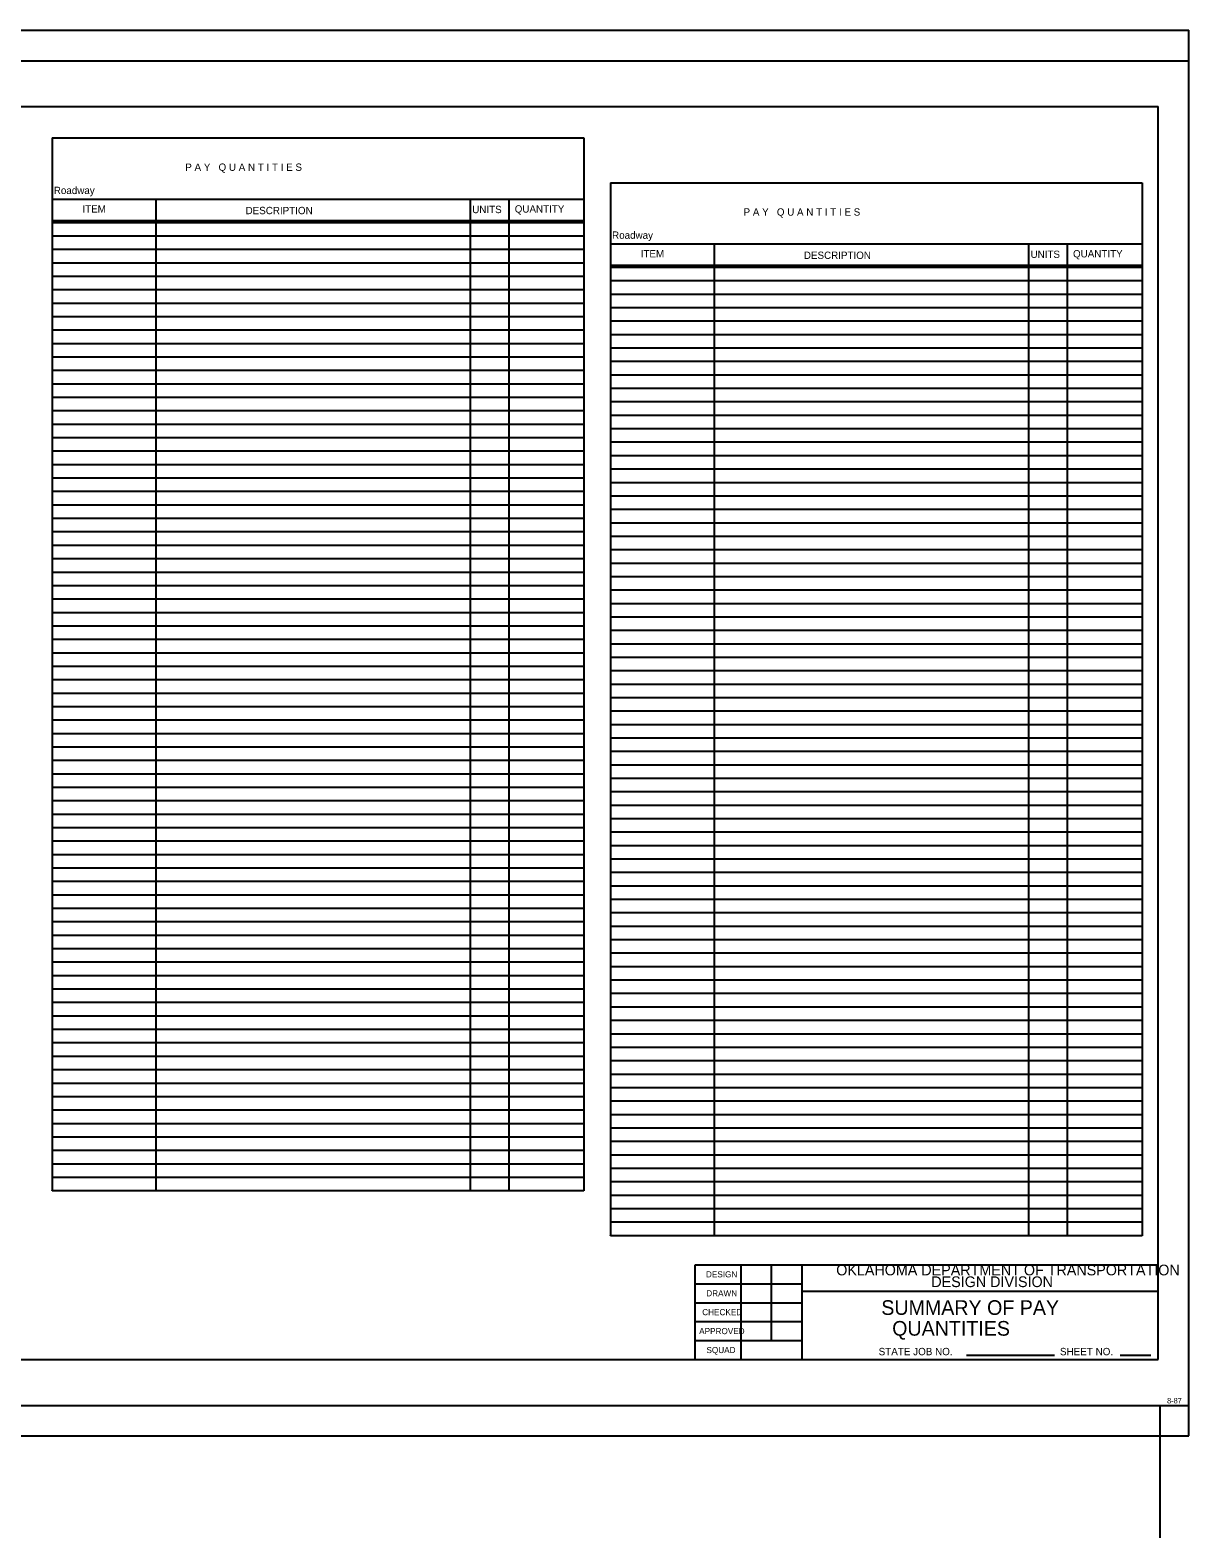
# Model space of a CAD drawing. Extents: x 1789800 to 1793399, y 1789140 to 1791776.
# Drawn here: x 1791505 to 1793399, y 1789140 to 1791606 of the extents above; entities that cross this region are included whole.
import ezdxf

# ---------------------------------------------------------------- set-up
doc = ezdxf.new("R2010")
doc.units = 0
for name, color, linetype in [('Level 1', 7, 'Continuous'), ('Level 2', 7, 'Continuous'), ('Level 20', 7, 'Continuous'), ('Level 21', 7, 'Continuous')]:
    doc.layers.add(name, color=color, linetype=linetype)

msp = doc.modelspace()

# ---------------------------------------------------------------- linework, layer by layer
at = {"layer": 'Level 2'}
for p, q in [((1791540.9, 1791430.2), (1792410.2, 1791430.2)), ((1791540.9, 1791430.2), (1791540.9, 1789707.4)), ((1792410.2, 1791430.2), (1792410.2, 1789707.4)), ((1792453.7, 1791356.9), (1793323.1, 1791356.9)), ((1792453.7, 1791356.9), (1792453.7, 1789634.2)), ((1793323.1, 1791356.9), (1793323.1, 1789634.2)), ((1791540.9, 1791330.2), (1792410.2, 1791330.2)), ((1791710.2, 1791330.2), (1791710.2, 1789708)), ((1792224.2, 1791330.2), (1792224.2, 1789708)), ((1792287.7, 1791329.9), (1792287.7, 1789707.6)), ((1791540.9, 1791295.2), (1792410.2, 1791295.2)), ((1791540.9, 1791292), (1792410.2, 1791292)), ((1791540.9, 1791270), (1792410.2, 1791270)), ((1792453.7, 1791256.9), (1793323.1, 1791256.9)), ((1792623.1, 1791256.9), (1792623.1, 1789634.7)), ((1793137.1, 1791256.9), (1793137.1, 1789634.7)), ((1793200.6, 1791256.6), (1793200.6, 1789634.4)), ((1791540.9, 1791248), (1792410.2, 1791248)), ((1791540.9, 1791226), (1792410.2, 1791226)), ((1792453.7, 1791221.9), (1793323.1, 1791221.9)), ((1792453.7, 1791218.7), (1793323.1, 1791218.7)), ((1791540.9, 1791204), (1792410.2, 1791204)), ((1791540.9, 1791182), (1792410.2, 1791182)), ((1792453.7, 1791196.7), (1793323.1, 1791196.7)), ((1791540.9, 1791160), (1792410.2, 1791160)), ((1792453.7, 1791174.7), (1793323.1, 1791174.7)), ((1791540.9, 1791138), (1792410.2, 1791138)), ((1792453.7, 1791152.7), (1793323.1, 1791152.7)), ((1791540.9, 1791116), (1792410.2, 1791116)), ((1792453.7, 1791130.7), (1793323.1, 1791130.7)), ((1792453.7, 1791108.7), (1793323.1, 1791108.7)), ((1791540.9, 1791094), (1792410.2, 1791094)), ((1792453.7, 1791086.7), (1793323.1, 1791086.7)), ((1791540.9, 1791072), (1792410.2, 1791072)), ((1792453.7, 1791064.7), (1793323.1, 1791064.7)), ((1791540.9, 1791050), (1792410.2, 1791050)), ((1792453.7, 1791042.7), (1793323.1, 1791042.7)), ((1791540.9, 1791028), (1792410.2, 1791028)), ((1792453.7, 1791020.7), (1793323.1, 1791020.7)), ((1791540.9, 1791006), (1792410.2, 1791006)), ((1791540.9, 1790984), (1792410.2, 1790984)), ((1792453.7, 1790998.7), (1793323.1, 1790998.7)), ((1791540.9, 1790962), (1792410.2, 1790962)), ((1792453.7, 1790976.7), (1793323.1, 1790976.7)), ((1791540.9, 1790940), (1792410.2, 1790940)), ((1792453.7, 1790954.7), (1793323.1, 1790954.7)), ((1791540.9, 1790918), (1792410.2, 1790918)), ((1792453.7, 1790932.7), (1793323.1, 1790932.7)), ((1792453.7, 1790910.7), (1793323.1, 1790910.7)), ((1791540.9, 1790896), (1792410.2, 1790896)), ((1792453.7, 1790888.7), (1793323.1, 1790888.7)), ((1791540.9, 1790874), (1792410.2, 1790874)), ((1792453.7, 1790866.7), (1793323.1, 1790866.7)), ((1791540.9, 1790852), (1792410.2, 1790852)), ((1792453.7, 1790844.7), (1793323.1, 1790844.7)), ((1791540.9, 1790830), (1792410.2, 1790830)), ((1792453.7, 1790822.7), (1793323.1, 1790822.7)), ((1791540.9, 1790808), (1792410.2, 1790808)), ((1792453.7, 1790800.7), (1793323.1, 1790800.7)), ((1791540.9, 1790786), (1792410.2, 1790786)), ((1791540.9, 1790764), (1792410.2, 1790764)), ((1792453.7, 1790778.7), (1793323.1, 1790778.7)), ((1791540.9, 1790742), (1792410.2, 1790742)), ((1792453.7, 1790756.7), (1793323.1, 1790756.7)), ((1791540.9, 1790720), (1792410.2, 1790720)), ((1792453.7, 1790734.7), (1793323.1, 1790734.7)), ((1792453.7, 1790712.7), (1793323.1, 1790712.7)), ((1791540.9, 1790698), (1792410.2, 1790698)), ((1792453.7, 1790690.7), (1793323.1, 1790690.7)), ((1791540.9, 1790676), (1792410.2, 1790676)), ((1792453.7, 1790668.7), (1793323.1, 1790668.7)), ((1791540.9, 1790654), (1792410.2, 1790654)), ((1792453.7, 1790646.7), (1793323.1, 1790646.7)), ((1791540.9, 1790632), (1792410.2, 1790632)), ((1792453.7, 1790624.7), (1793323.1, 1790624.7)), ((1791540.9, 1790610), (1792410.2, 1790610)), ((1792453.7, 1790602.7), (1793323.1, 1790602.7)), ((1791540.9, 1790588), (1792410.2, 1790588)), ((1791540.9, 1790566), (1792410.2, 1790566)), ((1792453.7, 1790580.7), (1793323.1, 1790580.7)), ((1791540.9, 1790544), (1792410.2, 1790544)), ((1792453.7, 1790558.7), (1793323.1, 1790558.7)), ((1791540.9, 1790522), (1792410.2, 1790522)), ((1792453.7, 1790536.7), (1793323.1, 1790536.7)), ((1791540.9, 1790500), (1792410.2, 1790500)), ((1792453.7, 1790514.7), (1793323.1, 1790514.7)), ((1792453.7, 1790492.7), (1793323.1, 1790492.7)), ((1791540.9, 1790478), (1792410.2, 1790478)), ((1792453.7, 1790470.7), (1793323.1, 1790470.7)), ((1791540.9, 1790456), (1792410.2, 1790456)), ((1792453.7, 1790448.7), (1793323.1, 1790448.7)), ((1791540.9, 1790434), (1792410.2, 1790434)), ((1792453.7, 1790426.7), (1793323.1, 1790426.7)), ((1791540.9, 1790412), (1792410.2, 1790412)), ((1792453.7, 1790404.7), (1793323.1, 1790404.7)), ((1791540.9, 1790390), (1792410.2, 1790390)), ((1791540.9, 1790368), (1792410.2, 1790368)), ((1792453.7, 1790382.7), (1793323.1, 1790382.7)), ((1791540.9, 1790346), (1792410.2, 1790346)), ((1792453.7, 1790360.7), (1793323.1, 1790360.7)), ((1791540.9, 1790324), (1792410.2, 1790324)), ((1792453.7, 1790338.7), (1793323.1, 1790338.7)), ((1791540.9, 1790302), (1792410.2, 1790302)), ((1792453.7, 1790316.7), (1793323.1, 1790316.7)), ((1792453.7, 1790294.7), (1793323.1, 1790294.7)), ((1791540.9, 1790280), (1792410.2, 1790280)), ((1792453.7, 1790272.7), (1793323.1, 1790272.7)), ((1791540.9, 1790258), (1792410.2, 1790258)), ((1792453.7, 1790250.7), (1793323.1, 1790250.7)), ((1791540.9, 1790236), (1792410.2, 1790236)), ((1792453.7, 1790228.7), (1793323.1, 1790228.7)), ((1791540.9, 1790214), (1792410.2, 1790214)), ((1792453.7, 1790206.7), (1793323.1, 1790206.7)), ((1791540.9, 1790192), (1792410.2, 1790192)), ((1791540.9, 1790170), (1792410.2, 1790170)), ((1792453.7, 1790184.7), (1793323.1, 1790184.7)), ((1791540.9, 1790148), (1792410.2, 1790148)), ((1792453.7, 1790162.7), (1793323.1, 1790162.7)), ((1791540.9, 1790126), (1792410.2, 1790126)), ((1792453.7, 1790140.7), (1793323.1, 1790140.7)), ((1791540.9, 1790104), (1792410.2, 1790104)), ((1792453.7, 1790118.7), (1793323.1, 1790118.7)), ((1792453.7, 1790096.7), (1793323.1, 1790096.7)), ((1791540.9, 1790082), (1792410.2, 1790082)), ((1792453.7, 1790074.7), (1793323.1, 1790074.7)), ((1791540.9, 1790060), (1792410.2, 1790060)), ((1792453.7, 1790052.7), (1793323.1, 1790052.7)), ((1791540.9, 1790038), (1792410.2, 1790038)), ((1792453.7, 1790030.7), (1793323.1, 1790030.7)), ((1791540.9, 1790016), (1792410.2, 1790016)), ((1792453.7, 1790008.7), (1793323.1, 1790008.7)), ((1791540.9, 1789994), (1792410.2, 1789994)), ((1792453.7, 1789986.7), (1793323.1, 1789986.7)), ((1791540.9, 1789972), (1792410.2, 1789972)), ((1791540.9, 1789950), (1792410.2, 1789950)), ((1792453.7, 1789964.7), (1793323.1, 1789964.7)), ((1791540.9, 1789928), (1792410.2, 1789928)), ((1792453.7, 1789942.7), (1793323.1, 1789942.7)), ((1791540.9, 1789906), (1792410.2, 1789906)), ((1792453.7, 1789920.7), (1793323.1, 1789920.7)), ((1792453.7, 1789898.7), (1793323.1, 1789898.7)), ((1791540.9, 1789884), (1792410.2, 1789884)), ((1792453.7, 1789876.7), (1793323.1, 1789876.7)), ((1791540.9, 1789862), (1792410.2, 1789862)), ((1792453.7, 1789854.7), (1793323.1, 1789854.7)), ((1791540.9, 1789840), (1792410.2, 1789840)), ((1792453.7, 1789832.7), (1793323.1, 1789832.7)), ((1791540.9, 1789818), (1792410.2, 1789818)), ((1792453.7, 1789810.7), (1793323.1, 1789810.7)), ((1791540.9, 1789796), (1792410.2, 1789796)), ((1792453.7, 1789788.7), (1793323.1, 1789788.7)), ((1791540.9, 1789774), (1792410.2, 1789774)), ((1791540.9, 1789752), (1792410.2, 1789752)), ((1792453.7, 1789766.7), (1793323.1, 1789766.7)), ((1791540.9, 1789730), (1792410.2, 1789730)), ((1792453.7, 1789744.7), (1793323.1, 1789744.7)), ((1791540.9, 1789708), (1792410.2, 1789708)), ((1791540.9, 1789707.4), (1791540.9, 1789708)), ((1792453.7, 1789722.7), (1793323.1, 1789722.7)), ((1792453.7, 1789700.7), (1793323.1, 1789700.7)), ((1792453.7, 1789678.7), (1793323.1, 1789678.7)), ((1792453.7, 1789656.7), (1793323.1, 1789656.7)), ((1792453.7, 1789634.7), (1793323.1, 1789634.7)), ((1792453.7, 1789634.2), (1792453.7, 1789634.7))]:
    msp.add_line(p, q, dxfattribs=at)
at = {"layer": 'Level 20'}
for p, q in [((1789800.3, 1791606.5), (1793399.5, 1791606.5)), ((1793399.5, 1789306.5), (1793399.5, 1791606.5)), ((1789950.3, 1791556.5), (1793399.5, 1791556.5)), ((1790100.2, 1791481.5), (1793349.5, 1791481.5)), ((1793349.5, 1789431.5), (1793349.5, 1791481.5)), ((1793349.5, 1790481.2), (1793349.5, 1790481.2)), ((1792592.3, 1789431.6), (1792592.3, 1789586.5)), ((1792592.3, 1789586.5), (1793349.6, 1789586.5)), ((1792667.3, 1789431.6), (1792667.3, 1789586.5)), ((1792717.3, 1789462.6), (1792717.3, 1789586.5)), ((1792767.2, 1789431.6), (1792767.2, 1789586.5)), ((1792592.3, 1789555.5), (1792767.2, 1789555.5)), ((1792767.2, 1789543.5), (1793349.5, 1789543.5)), ((1792592.3, 1789524.5), (1792767.2, 1789524.5)), ((1792592.3, 1789493.6), (1792767.2, 1789493.6)), ((1792592.3, 1789462.6), (1792767.2, 1789462.6)), ((1790100.2, 1789431.5), (1793349.5, 1789431.5)), ((1793036, 1789438.6), (1793180, 1789438.6)), ((1793287.2, 1789438.6), (1793287.2, 1789438.6)), ((1793287.2, 1789438.6), (1793337.4, 1789438.6)), ((1793287.4, 1789438.5), (1793287.4, 1789438.5)), ((1793337.4, 1789438.6), (1793337.4, 1789438.6)), ((1789950.3, 1789356.5), (1793399.5, 1789356.5)), ((1789800.3, 1789306.5), (1793399.5, 1789306.5)), ((1793352.8, 1789139.9), (1793352.8, 1789306.5))]:
    msp.add_line(p, q, dxfattribs=at)
at = {"layer": 'Level 21'}
msp.add_line((1793352.8, 1789306.5), (1793352.8, 1789356.5), dxfattribs=at)

# ---------------------------------------------------------------- texts
at = {"layer": 'Level 1'}
for s, p in [('SUMMARY OF PAY', (1792896.6, 1789504.6)), ('  QUANTITIES', (1792896.6, 1789470.6))]:
    msp.add_text(s, height=24, dxfattribs=at).set_placement(p)
at = {"layer": 'Level 2'}
for s, p in [('P A Y   Q U A N T I T I E S', (1791758.5, 1791376.3)), ('Roadway', (1791543.5, 1791338.3)), ('ITEM', (1791590.3, 1791308)), ('DESCRIPTION', (1791857.1, 1791305.4)), ('UNITS', (1792227.7, 1791307.1)), ('QUANTITY', (1792297.2, 1791308)), ('P A Y   Q U A N T I T I E S', (1792671.4, 1791303)), ('Roadway', (1792456.4, 1791265.1)), ('ITEM', (1792503.2, 1791234.7)), ('DESCRIPTION', (1792770, 1791232.2)), ('UNITS', (1793140.6, 1791233.8)), ('QUANTITY', (1793210.1, 1791234.7))]:
    msp.add_text(s, height=12, dxfattribs=at).set_placement(p)
at = {"layer": 'Level 20'}
for s, height, p in [('OKLAHOMA DEPARTMENT OF TRANSPORTATION', 17.5, (1792822.9, 1789569.3)), ('DESIGN', 10, (1792609.9, 1789566)), ('DESIGN DIVISION', 17.5, (1792978.4, 1789550.1)), ('DRAWN', 10, (1792610.4, 1789535)), ('APPROVED', 10, (1792598.8, 1789473.1)), ('STATE JOB NO. ', 12.055, (1792892.3, 1789438.6)), ('SHEET NO. ', 12.05, (1793188.8, 1789438.6)), ('8-87', 9, (1793363.9, 1789359.8))]:
    msp.add_text(s, height=height, dxfattribs=at).set_placement(p)
for s, rotation, p in [('CHECKED', 359.9964, (1792603.8, 1789504.1)), ('SQUAD', 0.0028, (1792610.7, 1789442.1))]:
    msp.add_text(s, height=10, rotation=rotation, dxfattribs=at).set_placement(p)

doc.saveas('drawing.dxf')
